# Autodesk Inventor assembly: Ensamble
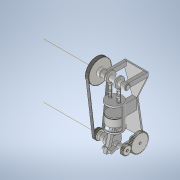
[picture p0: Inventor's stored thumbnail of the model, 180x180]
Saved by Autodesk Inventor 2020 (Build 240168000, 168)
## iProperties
Created: 2019-09
Part Number: Ensamble
Document SubType Name: Assembly
Designer: user
Author: user
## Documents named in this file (10)
- C:\Users\user\Documents\EIA\Cursos\Diseño asistido por computador\Parcial\2019-II\Archivos BancoDP  video Youtube\Ensamble.iam
- C:\Users\user\Documents\EIA\Cursos\Diseño asistido por computador\Parcial\2019-II\Archivos BancoDP  video Youtube\Bloque del motor.ipt
- C:\Users\user\Documents\EIA\Cursos\Diseño asistido por computador\Parcial\2019-II\Archivos BancoDP  video Youtube\Cigueñal.ipt
- C:\Users\user\Documents\EIA\Cursos\Diseño asistido por computador\Parcial\2019-II\Archivos BancoDP  video Youtube\Ensamble\Design Accelerator\Spur Gears1.iam
- C:\Users\user\Documents\EIA\Cursos\Diseño asistido por computador\Parcial\2019-II\Archivos BancoDP  video Youtube\Ensamble\Design Accelerator\Synchronous Belts Transmission1.iam
- C:\Users\user\Documents\EIA\Cursos\Diseño asistido por computador\Parcial\2019-II\Archivos BancoDP  video Youtube\Shaft1.ipt
- C:\Users\user\Documents\EIA\Cursos\Diseño asistido por computador\Parcial\2019-II\Archivos BancoDP  video Youtube\Leva.ipt
- C:\Users\user\Documents\EIA\Cursos\Diseño asistido por computador\Parcial\2019-II\Archivos BancoDP  video Youtube\Válvula.ipt
- C:\Users\user\Documents\EIA\Cursos\Diseño asistido por computador\Parcial\2019-II\Archivos BancoDP  video Youtube\Biela.ipt
- C:\Users\user\Documents\EIA\Cursos\Diseño asistido por computador\Parcial\2019-II\Archivos BancoDP  video Youtube\Pistón.ipt
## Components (11 placed, 9 different names)
1. Bloque del motor:1 — Insert:1, Mate:3, Mate:4, Mate:5, Flush:1, Mate:6, Mate:7, Mate:8, Flush:2
2. Cigueñal:1 — Insert:1, Mate:1, Mate:2, Angle:1, Angle:3, Insert:5
3. Spur Gears:1 [sub-assembly] — Mate:1, Mate:2, Mate:3, Mate:4, Angle:1
4. Synchronous Belts Transmission:1 [sub-assembly] — Angle:2, Angle:3, Insert:7
5. Shaft:1 — Angle:2, Insert:3, Insert:4, Angle:4, Angle:5, Insert:7
6. Leva:1 — Insert:4, Angle:5
7. Leva:2 — Insert:3, Angle:4
8. Válvula:1 — Mate:6, Mate:7
9. Válvula:2 — Mate:5, Flush:1
10. Biela:1 — Insert:5, Insert:6
11. Pistón:1 — Mate:8, Flush:2, Insert:6
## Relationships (21: Mate 8, Insert 6, Angle 5, Flush 2)
- Insert:1: Bloque del motor:1 ↔ Cigueñal:1
- Mate:1: Cigueñal:1 ↔ Spur Gears:1
- Mate:2: Cigueñal:1 ↔ Spur Gears:1
- Mate:3: Bloque del motor:1 ↔ Spur Gears:1
- Mate:4: Bloque del motor:1 ↔ Spur Gears:1
- Angle:1: Cigueñal:1 ↔ Spur Gears:1
- Angle:2: Synchronous Belts Transmission:1 ↔ Shaft:1
- Angle:3: Cigueñal:1 ↔ Synchronous Belts Transmission:1
- Insert:3: Shaft:1 ↔ Leva:2
- Insert:4: Shaft:1 ↔ Leva:1
- Mate:5: Bloque del motor:1 ↔ Válvula:2
- Flush:1: Bloque del motor:1 ↔ Válvula:2
- Mate:6: Bloque del motor:1 ↔ Válvula:1
- Mate:7: Bloque del motor:1 ↔ Válvula:1
- Insert:5: Cigueñal:1 ↔ Biela:1
- Mate:8: Bloque del motor:1 ↔ Pistón:1
- Flush:2: Bloque del motor:1 ↔ Pistón:1
- Insert:6: Biela:1 ↔ Pistón:1
- Angle:4: Shaft:1 ↔ Leva:2
- Angle:5: Shaft:1 ↔ Leva:1
- Insert:7: Synchronous Belts Transmission:1 ↔ Shaft:1
